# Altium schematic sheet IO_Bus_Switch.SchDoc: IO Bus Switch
size A4; DocumentNumber: 5; SheetNumber: 5; SheetTotal: 12
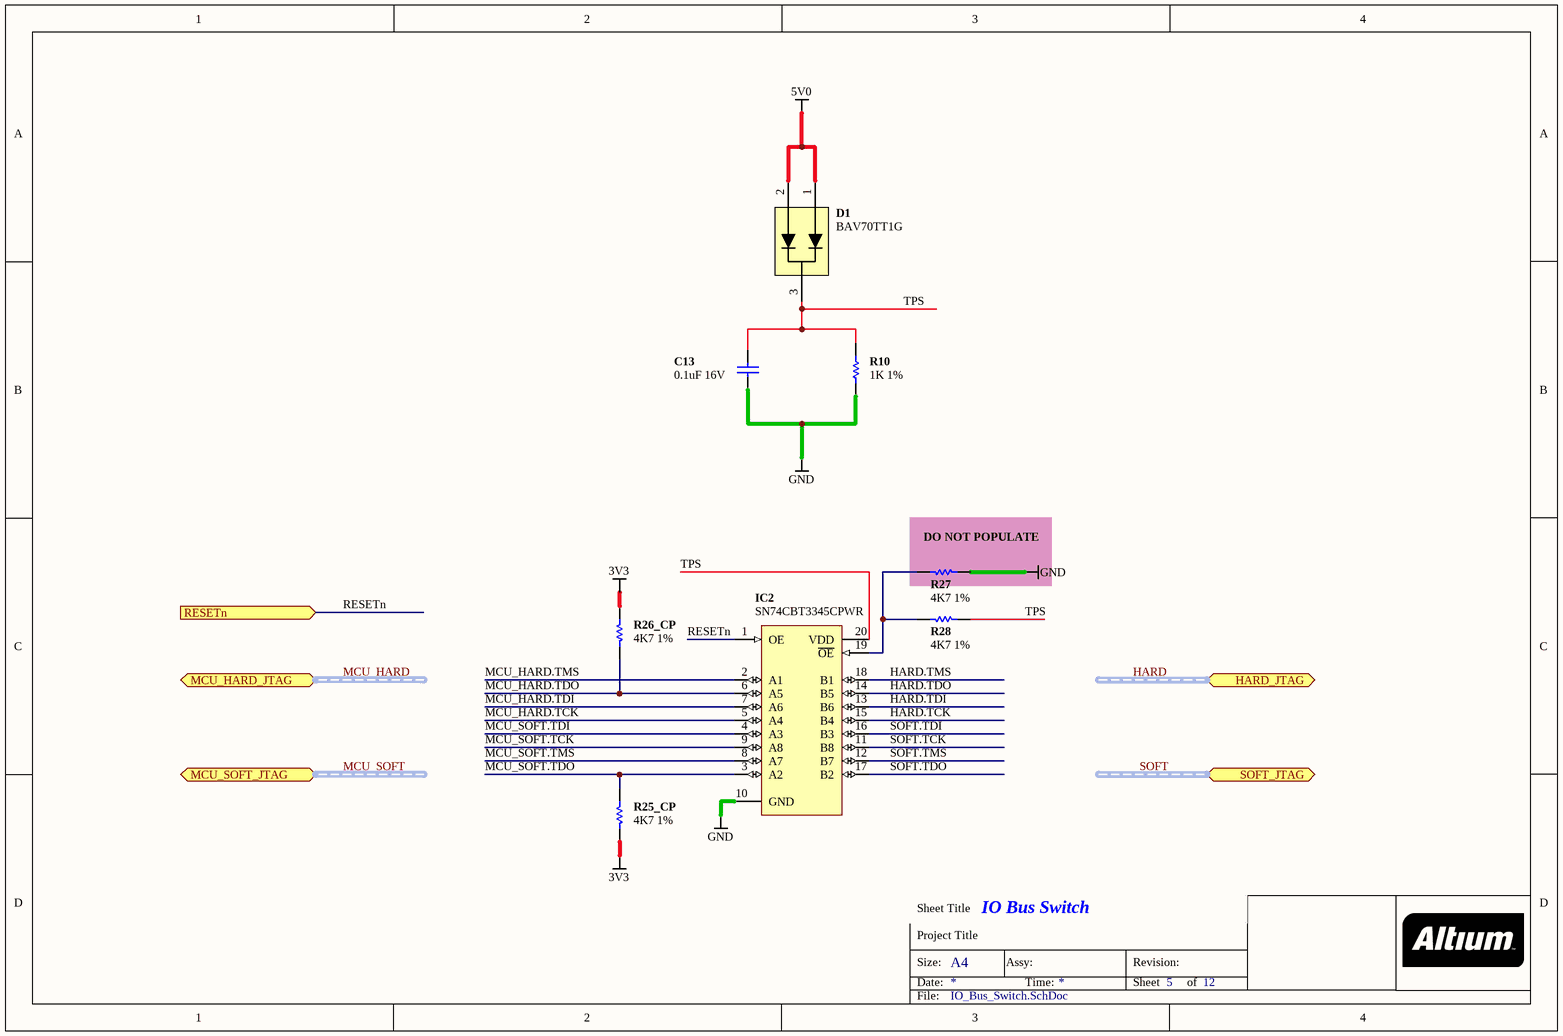
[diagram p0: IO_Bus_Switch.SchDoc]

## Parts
C13  0.1uF 16V  [CAPC1005-STAR]
D1  BAV70TT1G  [SOT95P230-3]
IC2  SN74CBT3345CPWR  [TSOP65P650-20]
R10  1K 1%  [RESC1005-STAR]
R25_CP  4K7 1%  [RESC1005-STAR]
R26_CP  4K7 1%  [RESC1005-STAR]
R27  4K7 1%  [RESC1005-STAR]  (no BOM)
R28  4K7 1%  [RESC1005-STAR]

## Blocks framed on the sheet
DO NOT POPULATE: R27

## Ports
HARD_JTAG (harness JTAG), MCU_HARD_JTAG (harness JTAG), MCU_SOFT_JTAG (harness JTAG), RESETn (in), SOFT_JTAG (harness JTAG)

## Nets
3V3: R25_CP.2 R26_CP.2
5V0: D1.1 D1.2
GND: C13.2 IC2.10(GND) R10.2 R27.1
HARD.TCK: IC2.15(B4)
HARD.TDI: IC2.13(B6)
HARD.TDO: IC2.14(B5)
HARD.TMS: IC2.18(B1)
MCU_HARD.TCK: IC2.5(A4)
MCU_HARD.TDI: IC2.7(A6)
MCU_HARD.TDO: IC2.6(A5) R26_CP.1
MCU_HARD.TMS: IC2.2(A1)
MCU_SOFT.TCK: IC2.9(A8)
MCU_SOFT.TDI: IC2.4(A3)
MCU_SOFT.TDO: IC2.3(A2) R25_CP.1
MCU_SOFT.TMS: IC2.8(A7)
RESETn: IC2.1(OE) ; port RESETn
SOFT.TCK: IC2.11(B8)
SOFT.TDI: IC2.16(B3)
SOFT.TDO: IC2.17(B2)
SOFT.TMS: IC2.12(B7)
TPS: C13.1 D1.3 IC2.20(VDD) R10.1 R28.1
NetIC2_19: IC2.19(~{OE}) R27.2 R28.2

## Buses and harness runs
harness HARD = port HARD_JTAG
harness MCU_HARD = port MCU_HARD_JTAG
harness MCU_SOFT = port MCU_SOFT_JTAG
harness SOFT = port SOFT_JTAG

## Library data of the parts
C13 = D-101-0080: Capacitor, Ceramic, 0.1uF 10% 16V 0402 (1005) X7R; Polarity: Non-Polarized
D1 = D-155-0000: Dual Switching Diode; Max Forward Current: 200 mA; Rated Voltage: 70 V
IC2 = D-205-0005: SN74CBT3345CPWR; HIGH SPEED 8-BIT BUS SWITCH
R10 = D-100-0121: Resistor, 1K 1% 0402 (1005); Power Rating: 63 mW
R25_CP R26_CP R27 R28 = D-100-0088: Resistor, 4K7 1% 0402 (1005); Power Rating: 63 mW; Resistance: 4.7 K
